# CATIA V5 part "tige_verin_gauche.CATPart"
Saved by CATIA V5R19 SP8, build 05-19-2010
Part number: tige_verin_gauche
Bounding box of the stored display mesh (mm): x -735 to -615, y -48 to 48, z -248 to 812.5
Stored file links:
  G:\EU_thinkMotion\CFAO_2010\MMS_groupe2\MMS_groupe2\OK\mmartini\mmartiniCFAO\tige_verin_gauche.CATPart
  C:\Users\Mathieu Martini\Desktop\CFAO\Animation\CFAO.CATProduct
  G:\EU_thinkMotion\CFAO_2010\MMS_groupe2\MMS_groupe2\OK\mmartini\mmartiniCFAO\Squelette.CATPart
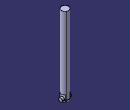
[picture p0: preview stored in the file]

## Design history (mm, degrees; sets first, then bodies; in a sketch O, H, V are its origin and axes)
External parameters (linked from other documents)
  External.diametre_verin = 120 mm
  External.diametre_canon = 150 mm
AxisSystem1: origin (0, 0, 0), X (1, 0, 0), Y (0, 1, 0), Z (0, 0, 1)
Set1
  Sketch1 on Plane1, origin (-675, 0, 0), H (0, 1, 0), V (0, 0, 1)
    line L1 (0, 812.5) -> (48, 812.5)
    line L2 (48, 812.5) -> (48, -200)
    line L3 (0, -200) -> (0, 812.5)
    point P3 (48, -200)
    point P4 (0, -200)
    arc A1 centre (0, -200) radius 48 from (0, -248) to (48, -200) ccw
    line L4 (0, -200) -> (0, -248)
    point P5 (0, -200)
    point P7 (48, -200)
    reference projected point E1 (0, -200) from Point1
    radius A1 = 48 {= (External.diametre_verin-External.diametre_verin /5)/2}
    length L3 = 1012.5 {= External.diametre_canon *6.75}
    horizontal: L1 H
    vertical: L2 V, L3 V, L4 V
    coincidence: A1 P3, P5 L3, P5 P4, L2 P7, P4 E1, P3 P7
    tangency: A1 L2
Set2
  Plane1 "Plan_verin_gauche": linked copy from another document
  Point1 "Point_verin_gauche": linked copy from another document
  Plane2 "Plan_rayon_int_verin_gauche": linked copy from another document
  Plane3 "Plan_rayon_ext_verin_gauche": linked copy from another document
Body1 (main body)
  Shaft1: profile Sketch1, axis Sketch1.L4, angle 360
  Sketch2 on Plane1, origin (-675, 0, 0), H (0, 1, 0), V (0, 0, 1)
    circle A1 centre (0, -200) radius 24
    point P1 (0, -200)
    reference projected point E1 (0, -200) from Point1
    radius A1 = 24 {= External.diametre_verin /5}
    coincidence: P1 E1
  Pad1: profile Sketch2, direction (1, 0, 0), up to Plane2, opposite side up to Plane3
  Sketch3 on Plane3, origin (-735, 0, 0), H (0, 1, 0), V (0, 0, 1)
    circle A1 centre (0, -200) radius 24
    point P1 (0, -200)
    reference projected point E1 (0, -200) from Point1
    line L1 (-60, -140) -> (60, -140)
    line L2 (60, -140) -> (60, -260)
    line L3 (60, -260) -> (-60, -260)
    line L4 (-60, -260) -> (-60, -140)
    radius A1 = 24 {= External.diametre_verin /5}
    length L2 = 120 {= External.diametre_verin}
    length L1 = 120 {= External.diametre_verin}
    distance P1 L1 = 60 {= External.diametre_verin /2}
    distance P1 L4 = 60 {= External.diametre_verin /2}
    coincidence: P1 E1
    horizontal: L1 H, L3 H
    vertical: L2 V, L4 V
  Pocket1: profile Sketch3, direction (-1, 0, 0), length -30 {= -External.diametre_verin /4}
  Sketch4 on Plane2, origin (-615, 0, 0), H (0, 1, 0), V (0, 0, 1)
    circle A1 centre (0, -200) radius 24
    point P1 (0, -200)
    reference projected point E1 (0, -200) from Point1
    line L1 (-60, -140) -> (60, -140)
    line L2 (60, -140) -> (60, -260)
    line L3 (60, -260) -> (-60, -260)
    line L4 (-60, -260) -> (-60, -140)
    radius A1 = 24 {= External.diametre_verin /5}
    length L1 = 120 {= External.diametre_verin}
    length L2 = 120 {= External.diametre_verin}
    distance P1 L1 = 60 {= External.diametre_verin /2}
    distance P1 L4 = 60 {= External.diametre_verin /2}
    coincidence: P1 E1
    horizontal: L1 H, L3 H
    vertical: L2 V, L4 V
  Pocket2: profile Sketch4, direction (-1, 0, 0), length 30 {= External.diametre_verin /4}
Relations
  Pad1.FirstLimit.Length = External.diametre_verin *0.75 (deactivated)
